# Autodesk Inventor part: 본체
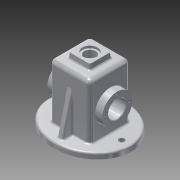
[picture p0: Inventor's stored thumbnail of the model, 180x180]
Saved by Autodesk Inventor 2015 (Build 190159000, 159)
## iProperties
Created: 2017-07
Part Number: 본체
Material: 알루미늄 6061
Document SubType Name: Modeling
Designer: C12
Density: 2.7 g/cm^3
Appearance: 알루미늄 - 평지
Mass: 889.87 g
Surface Area: 987.355 cm^2
Volume: 329.581 cm^3
Author: C12
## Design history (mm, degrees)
sketch "스케치1" dims "d63" = 75, "d64" = 65
  geometry: 2 further points; 1 other entity
  constraints: 2 coincident, 2 other
extrude "돌출1" new body sketch "스케치1" distance "d1" = 10; taper "d2" = 0 deg
sketch "스케치11"
  geometry: L1 (37, -37)-(-37, -37); L2 (-37, -37)-(-37, 37); L3 (-37, 37)-(37, 37); L4 (37, 37)-(37, -37); L5 (37, -37)-(-37, 37); L6 (-37, -37)-(37, 37); 1 further point
  constraints: 12 end point, 2 midpoint, 2 parallel, 1 horizontal, 1 perpendicular
  dimensions: "d65" = 74 distance of L2.end L3.end; "d66" = 74 distance of L1.end L2.end
extrude "돌출6" join sketch "스케치11" distance "d67" = 100; taper "d68" = 0 deg
sketch "스케치13"
  geometry: L1 (20, 20)-(-20, 20); L2 (-20, 20)-(-20, -20); L3 (-20, -20)-(20, -20); L4 (20, -20)-(20, 20); L5 (20, 20)-(-20, -20); L6 (-20, 20)-(20, -20); 1 further point
  constraints: 12 end point, 2 midpoint, 2 parallel, 1 horizontal, 1 perpendicular
  dimensions: "d69" = 40 distance of L3.end L2.end; "d70" = 40 distance of L2.end L1.end
extrude "돌출7" join sketch "스케치13" distance "d71" = 10; taper "d72" = -5 deg
sketch "스케치15"
  geometry: L1 (-10, 102)-(-10, -28) reference; C1 r 27.5 at (45, 37); 1 further point
  constraints: 1 centre point, 1 horizontal alignment
  dimensions: "d74" = 55 diameter of C1; "d75" = 55 distance from line of L1 C1.centre
extrude "돌출8" join sketch "스케치15" distance "d76" = 13; taper "d77" = 0 deg
sketch "스케치16"
  geometry: L1 (-37, 10)-(-37, 110) reference; L2 (37, 110)-(-37, 110) reference; L3 (37, 10)-(37, 110) reference; L4 (-75, 0)-(75, 0) reference; L5 (-32, 0)-(-32, 105) reference; L6 (-32, 105)-(32, 105); L7 (32, 105)-(32, 0) reference; 1 further point
  constraints: 6 end point, 2 point on line, 2 vertical
  dimensions: "d78" = 5 distance between parallel lines of L2 L6
extrude "돌출9" cut sketch "스케치16" stored distance "d79" = 64; taper "d80" = 0 deg
sketch "스케치17"
  geometry: 2 further points
  constraints: 1 coincident
hole "구멍5" sketch "스케치17" at (0, 0) diameter "d81" = 21; stored, may be unused: countersink angle "d85" = 90 deg, drill point angle "d87" = 0 deg; dims "d82" = 8, "d83" = 28, "d84" = 4, "d86" = 10
sketch "스케치19"
  geometry: C1 r 27.5 at (0, 0) reference; 2 further points
  constraints: 1 horizontal alignment
  dimensions: "d97" = 22.5 distance of C1.centre point (22.5, 0)
hole "구멍7" sketch "스케치19" at (22.5, 0) diameter "d98" = 3.242; stored, may be unused: countersink angle "d102" = 90 deg, drill point angle "d104" = 118 deg; dims "d99" = 8, "d100" = 28, "d101" = 4, "d103" = 10
sketch "스케치20"
  geometry: 3 further points
  constraints: 2 horizontal alignment
  dimensions: "d109" = 58 distance of point (0, 0) point (-58, 0); "d110" = 116 distance of point (58, 0) point (-58, 0)
hole "구멍8" sketch "스케치20" at (-58, 0), (58, 0) diameter "d111" = 10; stored, may be unused: countersink angle "d115" = 90 deg, drill point angle "d117" = 0 deg; dims "d112" = 8, "d113" = 28, "d114" = 4, "d116" = 20
sketch "스케치21"
  geometry: L1 (65, 10)-(-65, 10) reference; L2 (-65, 0)-(65, 0) reference; L3 (-37, 10)-(-37, 110) reference; L4 (-37, 82.194)-(-55, 10); L5 (65, 10)-(-65, 10) reference; L6 (-65, 0)-(65, 0) reference; L7 (-65, 0)-(-65, 10); L8 (0, 0)-(0, 10); L9 (65, 0)-(65, 10); L10 (37, 82.194)-(55, 10); 1 further point
  constraints: 10 end point, 4 symmetric about line, 2 point on line, 1 coincident, 1 midpoint, 1 vertical
  dimensions: "d119" = 10 horizontal distance of L2.start L4.end; "d120" = 14 deg angle of L7 L4; "d166" = 10 horizontal distance of point (65, 0) L10.end
feature "리브1" sketch "스케치21" dims "d121" = 1, "d122" = 10, "d123" = 0, "d124" = 0, "d125" = 1, "d126" = 1
sketch "스케치22"
  geometry: L1 (110, 17.875)-(110, 56.125) reference; L2 (0, 0)-(100, 0) reference; 2 further points
  constraints: 1 other
  dimensions: "d127" = 30 distance from line of point (80, 37) L1; "d128" = 37 distance from line of L2 point (80, 37)
feature "엠보싱1" sketch "스케치22" dims "d129" = 0.5, "d130" = 0
fillet "모깎기2" dims "d132" = 8
fillet "모깎기3" dims "d133" = 0.5
sketch "스케치23"
  geometry: L1 (32, 0)-(32, 105) reference; L2 (25, 55)-(25, 34.5); L3 (50, 55)-(25, 55) reference; L4 (32, 27.5)-(32, 55); L5 (50, 27.5)-(50, 82.5) reference; L6 (25, 34.5)-(32, 27.5); L7 (25, 75.5)-(32, 82.5); L8 (25, 55)-(25, 75.5); L9 (-14, 120)-(14, 120) reference; L10 (0, 120)-(0, 116.152); L11 (-25, 75.5)-(-32, 82.5); L12 (-25, 55)-(-25, 75.5); L13 (-50, 55)-(-25, 55); L14 (-25, 55)-(-25, 34.5); L15 (-25, 34.5)-(-32, 27.5)
  constraints: 24 end point, 8 symmetric about line, 4 point on line, 2 horizontal, 2 vertical, 1 horizontal alignment, 1 midpoint, 1 vertical alignment
  dimensions: "d135" = 7 distance between parallel lines of L2 L1; "d154" = 135 deg angle of L1 L6; "d164" = 55 distance of L4.start L7.end; "d165" = 55 distance of L15.end L11.end
revolve "회전3" sketch "스케치23" stored, may be unused: angle "d139" = 90 deg
hole "구멍9" diameter "d142" = 32; stored, may be unused: countersink angle "d146" = 90 deg, drill point angle "d148" = 0 deg; dims "d140" = 10, "d141" = 10, "d143" = 8, "d144" = 28, "d145" = 4, "d147" = 20
chamfer "모따기1" distance "d149" = 1; stored, may be unused: second distance "d150" = 2, angle "d151" = 45 deg
fillet "모깎기4" dims "d152" = 0.5
fillet "모깎기5" dims "d156" = 3
fillet "모깎기6" dims "d157" = 3
fillet "모깎기7" dims "d158" = 3
fillet "모깎기8" dims "d159" = 3
fillet "모깎기9" dims "d160" = 3
fillet "모깎기10" dims "d161" = 3
fillet "모깎기11" dims "d162" = 3
node "솔리드1"
pattern_circular "원형 패턴2" dims angle "d106" = 360 deg
mirror "대칭4"
mirror "대칭5"
mirror "대칭7"
node "투영된 루프1"
